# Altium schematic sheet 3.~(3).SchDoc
size 420 x 297 mm
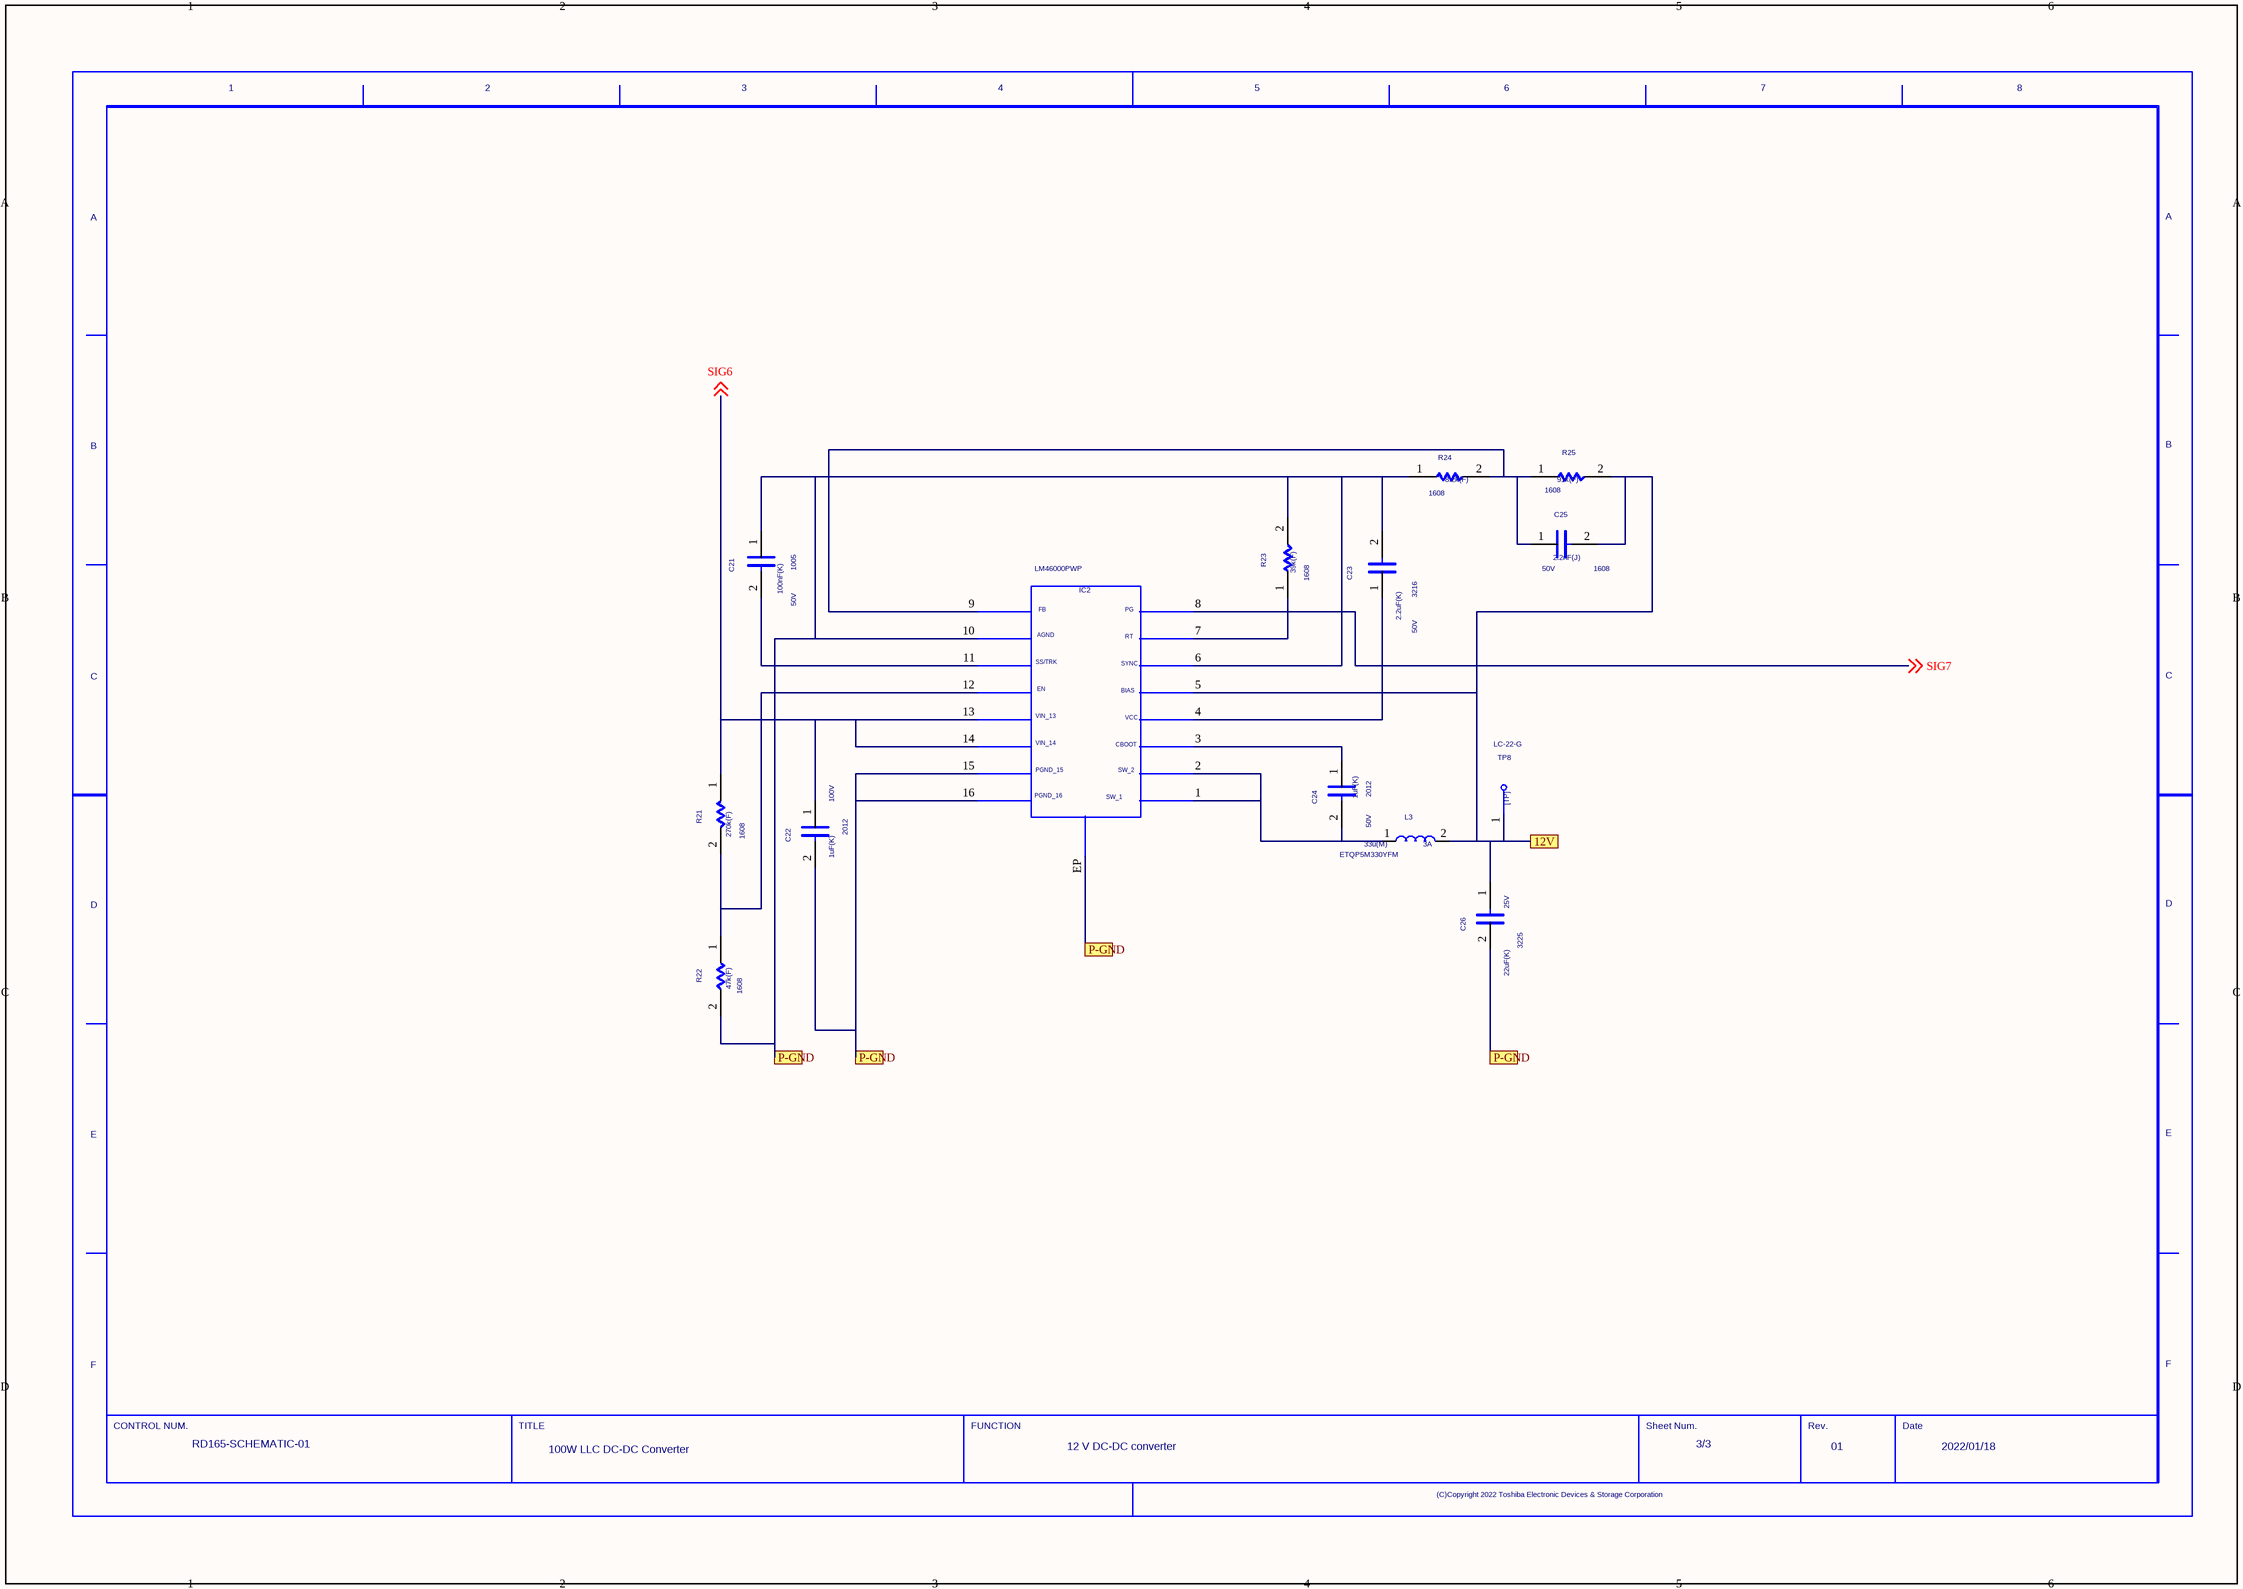
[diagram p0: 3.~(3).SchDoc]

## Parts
C21  SIZECODESMD: 1005  VAL2: 50V  VAL1: 100nF(K)  (hidden comment: C)
C22  SIZECODESMD: 2012  VAL2: 100V  VAL1: 1uF(K)  (hidden comment: C)
C23  SIZECODESMD: 3216  VAL2: 50V  VAL1: 2.2uF(K)  (hidden comment: C)
C24  SIZECODESMD: 2012  VAL2: 50V  VAL1: 1uF(K)  (hidden comment: C)
C25  SIZECODESMD: 1608  VAL2: 50V  VAL1: 2.2nF(J)  (hidden comment: C)
C26  SIZECODESMD: 3225  VAL2: 25V  VAL1: 22uF(K)  (hidden comment: C)
IC2  LM46000PWP
L3  VAL3: ETQP5M330YFM  VAL2: 3A  VAL1: 33u(M)  (hidden comment: L)
R21  SIZECODESMD: 1608  VAL1: 270k(F)  (hidden comment: R)
R22  SIZECODESMD: 1608  VAL1: 47k(F)  (hidden comment: R)
R23  SIZECODESMD: 1608  VAL1: 39k(F)  (hidden comment: R)
R24  SIZECODESMD: 1608  VAL1: 8.2k(F)  (hidden comment: R)
R25  SIZECODESMD: 1608  VAL1: 91k(F)  (hidden comment: R)
TP8  VAL3: LC-22-G  (hidden comment: TP)
U?  DATE: 2022/01/18  FUNCTION: 12 V DC-DC converter  REVISION: 01  SHEETNUMBER: 3/3  TITLE: 100W LLC DC-DC Converter  DRAWINGNUMBER: RD165-SCHEMATIC-01  (hidden comment: WAKU_DEF100)

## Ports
12V, P-GND

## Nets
P-GND: C21.1 C22.2 C23.2 C26.2 IC2.6 IC2.10 IC2.15 IC2.16 IC2.EP R22.2 R23.2 R24.1 ; port P-GND
SIG6: C22.1 IC2.13 IC2.14 R21.1 ; off-sheet SIG6
SIG7: IC2.8 ; off-sheet SIG7
SIG250: C23.1 IC2.4
SIG251: IC2.7 R23.1
SIG252: C25.2 C26.1 IC2.5 L3.2 R25.2 TP8.1 ; port 12V
SIG254: C21.2 IC2.11
SIG256: IC2.12 R21.2 R22.1
SIG257: C25.1 IC2.9 R24.2 R25.1
SIG258: C24.2 IC2.1 IC2.2 L3.1
SIG259: C24.1 IC2.3

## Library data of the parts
C21 = C: OriginalSymbolOrigin: (2540,7620); RATEDVOLTAGE: 50; MAXGCOUNT: 1; TEMPCHARACTERI2: B; OUMEMAKER: TDK ＴＤＫ; QUADMODEL: CON_100N; FNLEADFREETHET1GT2GMCTH1: N_N_N; OUMECLASSIFICATION: セラミックコンデンサ; CDBNAME: Chip1005_GS_2; NOMINALCAPACITA: 100n; OUMEMAKERKATAMEI: C1005JB0J104KT; CAPACITANCETOLE: K; CDMASTERCADCELG: DC834K; ADSMODELNAME: s_C1005JB0J104KT
C22 C24 = C: OriginalSymbolOrigin: (2540,7620); RATEDVOLTAGE: 50; MAXGCOUNT: 1; OUMEMAKER: TDK ＴＤＫ; QUADMODEL: CON_1U; FNLEADFREETHET1GT2GMCTH1: 3_2_N; OUMECLASSIFICATION: セラミックコンデンサ; CDBNAME: Chip2012_GS_1; NOMINALCAPACITA: 1u; PMPRODUCTSTYPEG: DA; OUMEMAKERKATAMEI: CGA4J3X7R1H105KT@@; CAPACITANCETOLE: K; CDMASTERCADCELG: KC0159; ADSMODELNAME: s_CGA4J3X7R1H105KT@@
C23 = C: OriginalSymbolOrigin: (2540,7620); RATEDVOLTAGE: 50; MAXGCOUNT: 1; OUMEMAKER: MRT 村田製作所; QUADMODEL: CON_2.2U; FNLEADFREETHET1GT2GMCTH1: 3_2_N; OUMECLASSIFICATION: セラミックコンデンサ; CDBNAME: Chip3216_GS_1; NOMINALCAPACITA: 2.2u; PMPRODUCTSTYPEG: HEV; OUMEMAKERKATAMEI: GCM31CR71H225KA55L@@; CAPACITANCETOLE: K; CDMASTERCADCELG: KC0137; ADSMODELNAME: s_GCM31CR71H225KA55L@@
C25 = C: OriginalSymbolOrigin: (2540,7620); RATEDVOLTAGE: 50; MAXGCOUNT: 1; TEMPCHARACTERI2: CH; OUMEMAKER: MRT 村田製作所; QUADMODEL: CON_2.2N; FNLEADFREETHET1GT2GMCTH1: N_N_N; OUMECLASSIFICATION: セラミックコンデンサ; CDBNAME: Chip1608_GS_1; NOMINALCAPACITA: 2.2n; PMPRODUCTSTYPEG: DA; OUMEMAKERKATAMEI: GRM1882C1H222JA01D@@; CAPACITANCETOLE: J; ADSMODELNAME: s_GRM1882C1H222JA01D@@
C26 = C#1: OriginalSymbolOrigin: (2540,7620); CaptureCellPackProp: C##1; RATEDVOLTAGE: 16; MAXGCOUNT: 1; OUMEMAKER: TDK ＴＤＫ; QUADMODEL: CON_22U; FNLEADFREETHET1GT2GMCTH1: N_N_N; OUMECLASSIFICATION: セラミックコンデンサ; CDBNAME: Chip3225_GS; NOMINALCAPACITA: 22u; OUMEMAKERKATAMEI: (SV)C3225X7R1C226K250AC; CAPACITANCETOLE: K; CDMASTERCADCELG: KCK0271; ADSMODELNAME: s__SV_C3225X7R1C226K250AC
IC2 = LM46000PWP: SAVEAREA0: -78128,-18763,121485,85972; SAVECOUNT: 11; TIME: 10:30:02; UPDATEUSER: t5459927; UPDATETIME: 09:42:03; OriginalSymbolOrigin: (0,45720); CDBNAME: LM46000PWP_GS
L3 = L: OriginalSymbolOrigin: (2540,5080); CDBNAME: ETQP5M***Y*M_PN
R21 = R: OriginalSymbolOrigin: (5080,5080); MAXGCOUNT: 1; OUMEMAKER: KOA コーア; QUADMODEL: RES_270K; MOUNTINGFORMSMD: SMD; FNLEADFREETHET1GT2GMCTH1: 3_1_N; OUMECLASSIFICATION: 表面実装用固定抵抗器; CDBNAME: Chip1608_GS_1; RESISTANCETOLER: D; PMPRODUCTSTYPEG: HEV; POWERRATING: 100m; OUMEMAKERKATAMEI: RK73H1JTTD2703D@@; NOMINALRESISTAN: 270K; VAL2: 100mW; CDMASTERCADCELG: KC0133; ADSMODELNAME: s_RK73H1JTTD2703D@@
R22 = R: OriginalSymbolOrigin: (5080,5080); MAXGCOUNT: 1; OUMEMAKER: KOA コーア; QUADMODEL: RES_47K; MOUNTINGFORMSMD: SMD; FNLEADFREETHET1GT2GMCTH1: 3_1_N; OUMECLASSIFICATION: 表面実装用固定抵抗器; CDBNAME: Chip1608_GS_1; RESISTANCETOLER: F; POWERRATING: 63m; OUMEMAKERKATAMEI: RK73H1JTD4702F; NOMINALRESISTAN: 47K; VAL2: 100mW; CDMASTERCADCELG: DR802R; ADSMODELNAME: s_RK73H1JTD4702F
R23 = R: OriginalSymbolOrigin: (5080,5080); MAXGCOUNT: 1; OUMEMAKER: HDK 北陸電気工業; QUADMODEL: RES_39K; MOUNTINGFORMSMD: SMD; FNLEADFREETHET1GT2GMCTH1: 3_1_N; OUMECLASSIFICATION: 表面実装用固定抵抗器; CDBNAME: Chip1608_GS_1; RESISTANCETOLER: F; POWERRATING: 63m; OUMEMAKERKATAMEI: CR1/16 393FV; NOMINALRESISTAN: 39K; VAL2: 100mW; CDMASTERCADCELG: DR802R; ADSMODELNAME: s_CR1_16_393FV
R24 = R: OriginalSymbolOrigin: (5080,5080); MAXGCOUNT: 1; OUMEMAKER: KOA コーア; QUADMODEL: RES_8.2K; MOUNTINGFORMSMD: SMD; FNLEADFREETHET1GT2GMCTH1: N_N_N; OUMECLASSIFICATION: 表面実装用固定抵抗器; CDBNAME: Chip1608_GS_1; RESISTANCETOLER: F; PMPRODUCTSTYPEG: DME; POWERRATING: 100m; OUMEMAKERKATAMEI: RK73H1JRTTD8201F; NOMINALRESISTAN: 8.2K; VAL2: 100mW; CDMASTERCADCELG: KCK0203; ADSMODELNAME: s_RK73H1JRTTD8201F
R25 = R: OriginalSymbolOrigin: (5080,5080); MAXGCOUNT: 1; OUMEMAKER: NAE パナソニックエレクトロニックデバイス; QUADMODEL: RES_91K; MOUNTINGFORMSMD: SMD; FNLEADFREETHET1GT2GMCTH1: N_N_N; OUMECLASSIFICATION: 表面実装用固定抵抗器; CDBNAME: Chip1608_GS_1; RESISTANCETOLER: F; PMPRODUCTSTYPEG: DA; POWERRATING: 100m; OUMEMAKERKATAMEI: ERJ3EKF9102V@@; NOMINALRESISTAN: 91K; VAL2: 100mW; CDMASTERCADCELG: KC0161; ADSMODELNAME: s_ERJ3EKF9102V@@
TP8 = TP: TIME: 16:12:21; UPDATEUSER: fukuda-y; UPDATETIME: 16:18:11; SAVECOUNT: 2; SAVEAREA0: -242,-92,12810,7836; OriginalSymbolOrigin: (0,7620); CDBNAME: LC-22_GS
U? = WAKU_DEF100: PLOTTIME: HH:MM; SAVEAREA0: 198008,-65938,436964,90161; TIME: 14:30:25; UPDATEUSER: t5459927; UPDATETIME: 11:03:12; SAVECOUNT: 4; OriginalSymbolOrigin: (10160,284480)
